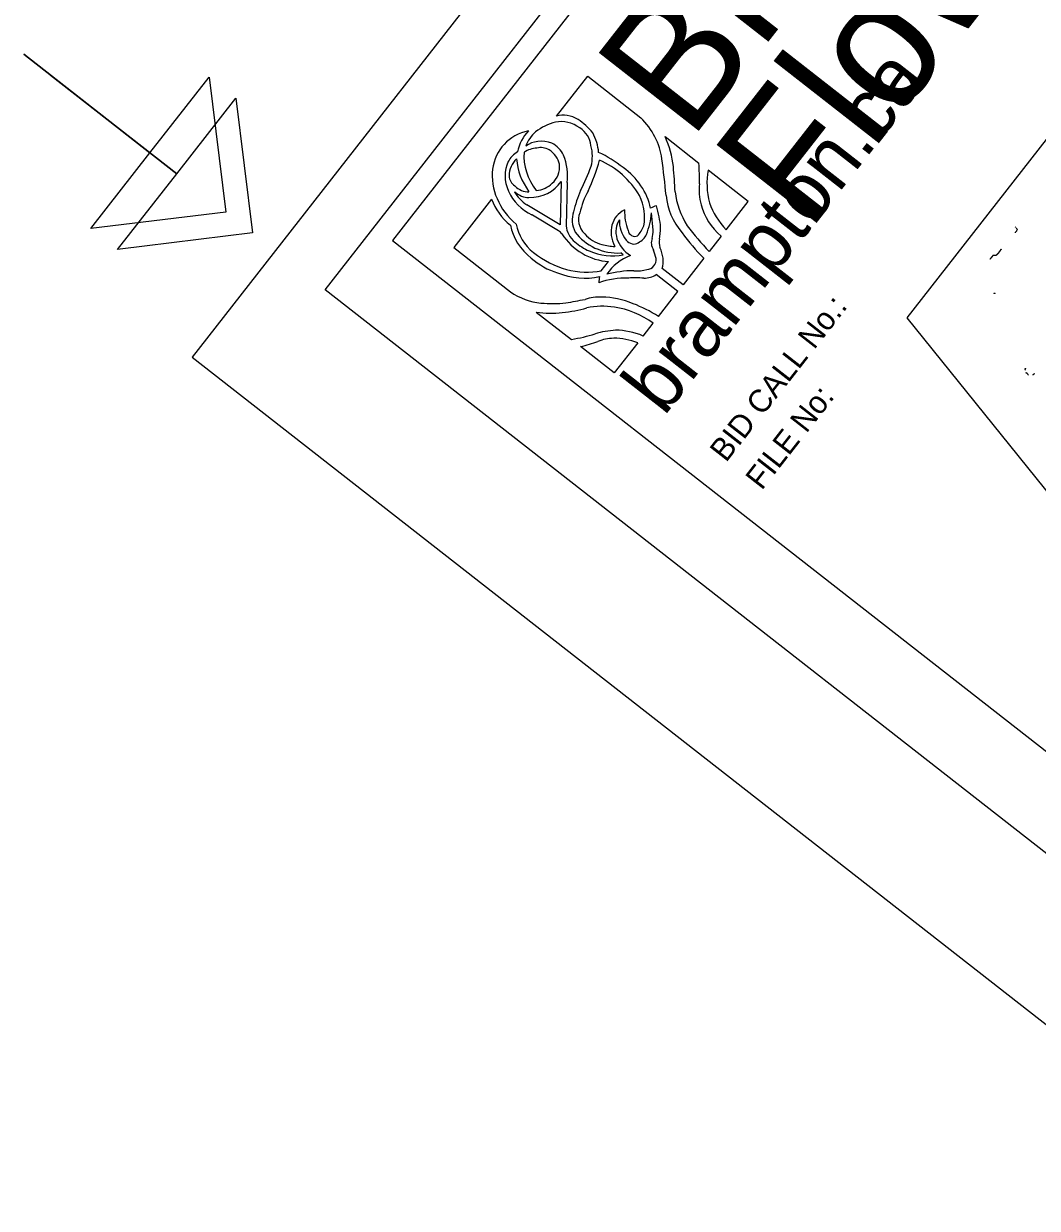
# Model space of a CAD drawing. Extents: x 570310 to 627788, y 4814773 to 4874073.
# Drawn here: x 570310 to 590442, y 4818457 to 4841980 of the extents above; entities that cross this region are included whole.
import ezdxf

# ---------------------------------------------------------------- set-up
doc = ezdxf.new("R2010")
doc.units = 0
for name, color, linetype in [('-PRINT FULLSIZE', 7, 'Continuous'), ('-PRINT HALFSIZE', 7, 'Continuous'), ('ENG_BORDER', 7, 'Continuous'), ('ENG_LOGO', 7, 'Continuous'), ('ENG_TX_BORDER', 7, 'Continuous'), ('ENG_TX_LOGO', 7, 'Continuous'), ('ENG_TX_TITLEBLOCK', 7, 'Continuous'), ('ENG_WK_MISC-1', 7, 'Continuous'), ('GIS_EDGE-WATER', 7, 'Continuous')]:
    doc.layers.add(name, color=color, linetype=linetype)

msp = doc.modelspace()

# ---------------------------------------------------------------- linework, layer by layer
at = {"layer": '-PRINT FULLSIZE'}
msp.add_lwpolyline([(595286.9968, 4818456.8924), (620056.367, 4850160.2405), (598425.4731, 4867060.1469), (573656.1029, 4835356.7988)], close=True, dxfattribs=at)
at = {"layer": '-PRINT HALFSIZE'}
msp.add_lwpolyline([(576300.1305, 4836693.9345), (598958.0147, 4865694.7038), (618744.9647, 4850235.4441), (596087.0805, 4821234.6748)], close=True, dxfattribs=at)
at = {"layer": 'ENG_BORDER'}
msp.add_lwpolyline([(596714.4064, 4822768.5365), (618113.3122, 4850157.887), (599035.5719, 4865063.0513), (577636.6661, 4837673.7008)], close=True, dxfattribs=at)
at = {"layer": 'ENG_LOGO'}
for p, q in [((580895.1142, 4840145.3957), (581513.5575, 4840936.9671)), ((581513.5575, 4840936.9671), (582566.8391, 4840114.0533)), ((583049.1476, 4839737.2326), (583720.5967, 4839212.6391)), ((584698.6494, 4838448.5006), (583903.4326, 4839069.7921)), ((580983.5243, 4838847.5352), (580966.4671, 4837986.3343)), ((581102.0815, 4838826.0463), (581085.0243, 4837964.8454)), ((579603.8661, 4838492.6735), (578854.626, 4837533.6899)), ((580966.4671, 4837986.3343), (580302.4381, 4838384.2037)), ((584262.1791, 4837889.844), (584698.6494, 4838448.5006)), ((580935.4209, 4837866.4397), (580413.2776, 4838179.2948)), ((582813.6306, 4837880.4538), (582781.5828, 4838223.1458)), ((584163.2056, 4837763.1638), (583924.0199, 4837457.02)), ((578854.626, 4837533.6899), (579976.6595, 4836657.0612)), ((582217.4199, 4837389.3826), (582169.062, 4837427.164)), ((581782.586, 4837074.2794), (581926.0648, 4837257.9239)), ((583406.4713, 4836794.5881), (582992.688, 4837117.871)), ((583818.8606, 4837322.4222), (583406.4713, 4836794.5881)), ((583303.374, 4836662.6295), (582870.5051, 4837000.8238)), ((582915.7281, 4836166.4654), (583303.374, 4836662.6295)), ((580491.7344, 4836254.6406), (581187.7589, 4835710.8467)), ((582612.622, 4835778.5072), (582812.6308, 4836034.5068)), ((582039.7179, 4835045.2234), (581370.5948, 4835567.9997)), ((582505.4008, 4835641.2704), (582039.7179, 4835045.2234))]:
    msp.add_line(p, q, dxfattribs=at)
for centre, major_axis, start_param, end_param in [((581109.4813, 4839682.6824), (-419.3161, 327.6057), 4.8589663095, 5.7337363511), ((581380.207, 4838850.902), (-1055.7418, 824.8359), 5.7058114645, 6.0887938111), ((581076.7864, 4839521.9825), (-449.494, 351.1832), 4.7474532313, 5.6817521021), ((580799.8617, 4839251.149), (917.6584, -716.9533), 1.3167113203, 1.6562678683), ((581708.5742, 4839346.5141), (1078.6552, -842.7378), 0.7124777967, 1.4213712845), ((580771.0112, 4838771.248), (-967.9774, 756.2669), 5.6782325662, 7.8074967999), ((581243.3289, 4839050.0378), (-956.7925, 747.5282), 6.2099250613, 6.6775824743), ((581108.2715, 4839163.6651), (-726.8956, 567.9131), 6.1040163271, 6.5523835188), ((581159.7543, 4839592.1523), (-350.6726, 273.9754), 3.823834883, 4.8073067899), ((580771.2477, 4839512.7997), (803.7482, -627.9569), 0.6541881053, 1.0848737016), ((581313.4694, 4839267.1015), (1598.9524, -1249.2385), 0.6826869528, 1.0105277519), ((580626.8192, 4838972.9699), (-469.0218, 366.44), 5.5146652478, 6.0255895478), ((580689.3518, 4839082.5296), (-492.3035, 384.6297), 5.1001923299, 6.0586546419), ((580636.9521, 4839210.7881), (-269.6248, 210.654), 4.9345522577, 5.7209047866), ((580551.2028, 4839174.2787), (340.6053, -266.1101), 0.7855120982, 1.6409488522), ((580624.3392, 4839239.6111), (-383.2821, 299.4528), 4.1958742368, 4.894963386), ((580696.8835, 4839494.2226), (760.2966, -594.0088), 0.3442010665, 0.8318041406), ((580644.4488, 4838838.9882), (647.2744, -505.7061), 3.3189857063, 4.9765849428), ((580479.6761, 4838921.7788), (-501.0843, 391.4899), 5.9370417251, 6.4438162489), ((580521.423, 4838859.9081), (-478.4823, 373.8314), 6.1188819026, 6.855524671), ((581220.4051, 4839163.3753), (-938.3041, 733.0835), 0.6287743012, 1.2559646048), ((581286.267, 4839164.9188), (-869.9484, 679.6782), 0.4842775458, 1.2767125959), ((579925.6813, 4839150.693), (991.437, -774.5955), 0.4608611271, 0.9459223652), ((577521.288, 4840914.9375), (3634.6579, -2839.7059), 0.1774553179, 0.3449817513), ((581127.0734, 4837748.7457), (1650.74, -1289.6995), 1.5652885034, 1.8399595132), ((581350.6476, 4838066.6462), (-1172.8347, 916.3189), 4.2733940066, 5.0058082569), ((561895.012, 4840216.7186), (17792.8211, -13901.2754), 0.6698057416, 0.7058083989), ((580422.482, 4839220.5415), (443.6506, -346.6179), 6.0985748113, 6.9695368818), ((576306.4573, 4841616.0493), (4636.6717, -3622.5649), 0.16181878, 0.2678120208), ((581640.5165, 4838282.4461), (958.684, -749.006), 0.7809699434, 1.6238235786), ((572292.0029, 4840016.7327), (9175.9719, -7169.055), 0.6194507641, 0.6675514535), ((577516.3638, 4839849.6279), (5202.9676, -4065.0038), 0.5738028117, 0.6437425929), ((585595.6575, 4838532.4264), (-1434.863, 1121.0378), 0.4176868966, 0.8184571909), ((580203.4199, 4838936.5287), (-213.1452, 166.5273), 0.6660468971, 1.5760265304), ((580275.1671, 4838945.9347), (-264.5665, 206.702), 1.423327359, 2.3769176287), ((580193.5153, 4839399.7451), (759.9994, -593.7766), 5.4553846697, 6.3466755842), ((580330.1636, 4839240.3471), (504.85, -394.432), 5.5589353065, 6.1986415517), ((584764.1825, 4838500.3192), (-870.4131, 680.0412), 0.4452460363, 0.8692931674), ((580585.2873, 4838856.425), (-516.9259, 403.8667), 1.1195514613, 1.6743983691), ((580428.5899, 4839179.1346), (614.3942, -480.0173), 4.7586960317, 4.9747194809), ((580280.9036, 4838790.588), (228.3375, -178.3968), 4.9898137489, 5.5158032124), ((584281.1905, 4837117.4566), (-2614.249, 2042.4752), 0.2071058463, 0.3649970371), ((583601.192, 4837409.7711), (-1919.1286, 1499.3876), 0.1473665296, 0.3720968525), ((581611.4627, 4838302.5685), (862.7622, -674.0637), 0.4013046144, 1.0207469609), ((584250.16, 4838455.3753), (-991.1305, 774.356), 0.6523004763, 1.3369389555), ((584777.6884, 4838550.9608), (-1288.3363, 1006.5586), 0.690533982, 1.1577139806), ((580492.7588, 4838640.8819), (-788.11, 615.739), 0.9158280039, 1.5687165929), ((582581.9828, 4837749.0811), (-507.647, 396.6173), 5.8789198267, 7.3683806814), ((583252.3059, 4838071.4386), (-843.1948, 658.776), 0.5321884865, 0.9577271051), ((583064.8195, 4837918.407), (-398.5119, 311.3516), 5.6956161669, 5.9785433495), ((580720.5623, 4838115.7052), (1881.8402, -1470.2547), 0.6640190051, 0.8656308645), ((584775.2991, 4838455.4642), (-869.3041, 679.1748), 0.8241736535, 1.5199082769), ((585139.018, 4838632.4005), (-1074.7771, 839.7079), 0.9231161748, 1.3985304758), ((580380.6219, 4838117.7857), (65.2496, -50.9785), 1.7178886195, 1.8349922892), ((581783.1071, 4837994.5493), (-484.7976, 378.7654), 0.2845497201, 1.0288536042), ((581700.5678, 4838029.1459), (-312.1148, 243.8508), 0.1795880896, 1.4251032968), ((582569.7364, 4837771.2011), (416.6051, -325.4876), 3.1733767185, 4.8655067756), ((582659.8973, 4837951.5721), (-433.4004, 338.6095), 0.4777442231, 1.3245705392), ((580697.2995, 4838755.1335), (1752.4651, -1369.1758), 0.2526400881, 0.4825595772), ((580913.8958, 4837994.6653), (-798.8602, 624.138), 0.7643207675, 1.5717221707), ((580879.3938, 4837989.6404), (-666.3815, 520.6343), 0.7413901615, 1.5637538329), ((580870.1095, 4837743.4213), (-130.4991, 101.9571), 4.3258897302, 4.8594812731), ((581811.8142, 4838204.2596), (-827.6886, 646.6612), 1.1842970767, 2.265824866), ((581489.1919, 4837920.7898), (-338.8027, 264.7017), 0.6370603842, 1.5405225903), ((581893.0117, 4838220.416), (-679.4012, 530.8064), 1.258523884, 1.8538737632), ((581826.1035, 4838071.432), (-425.5097, 332.4446), 1.3269106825, 2.0906940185), ((582431.1775, 4837866.748), (-96.9735, 75.764), 0.6934943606, 2.7954406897), ((581836.5339, 4838359.526), (701.6088, -548.1569), 6.2064134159, 6.5196171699), ((581599.0048, 4838127.4485), (1017.3849, -794.8682), 0.3900627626, 0.5372324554), ((581399.8809, 4838202.7278), (1306.6822, -1020.892), 0.4081491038, 0.5667561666), ((585778.9229, 4839131.4658), (-2500.7429, 1953.7945), 1.2235724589, 1.4346288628), ((587371.3177, 4840353.6116), (-4210.7678, 3289.8124), 1.2686065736, 1.395257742), ((581866.416, 4838376.4538), (895.5162, -699.654), 4.6862197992, 4.981796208), ((581914.5138, 4838268.7868), (620.4809, -484.7728), 5.1310282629, 5.4773020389), ((582403.8794, 4837762.5608), (-137.2504, 107.2317), 1.287529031, 2.8996417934), ((582250.4774, 4838036.5476), (390.2618, -304.9059), 5.8964106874, 6.4660989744), ((583042.8761, 4837585.0823), (-223.863, 174.9009), 0.214109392, 1.1533092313), ((583366.1691, 4837566.0401), (-362.3792, 283.1217), 0.4224034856, 0.821660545), ((581253.1562, 4838439.9326), (-1217.0748, 950.8831), 1.5557378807, 2.5226511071), ((581827.1209, 4838391.5769), (893.4609, -698.0482), 5.0194878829, 5.6658955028), ((581941.532, 4838362.449), (818.3835, -639.3913), 4.9954134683, 5.5264632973), ((583033.3397, 4836192.4071), (-1105.1575, 863.4437), 5.8232020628, 6.3340773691), ((581319.3434, 4837198.516), (1339.9159, -1046.857), 0.8288882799, 0.9384559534), ((582395.1724, 4837362.8683), (516.7857, -403.7572), 0.3240202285, 1.04896782), ((581073.5234, 4838049.3467), (-934.6845, 730.2556), 1.4938449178, 2.0023458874), ((582614.4912, 4837340.8751), (215.1815, -168.1182), 5.5817956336, 6.9415708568), ((581225.3227, 4838268.2229), (1170.7994, -914.7287), 5.0636804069, 5.674397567), ((582299.132, 4836754.0713), (-472.1143, 368.8562), 0.3655220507, 0.5978053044), ((582582.7927, 4835264.4236), (-1455.0093, 1136.7778), 5.4396406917, 5.8009467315), ((582925.165, 4834569.3006), (-2189.0357, 1710.2621), 5.4827327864, 5.6973383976), ((583781.4589, 4829492.6448), (-6495.8138, 5075.0859), 5.4413205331, 5.4802135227), ((582351.8851, 4837876.3398), (701.5498, -548.1108), 5.382988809, 5.7042643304), ((582566.2603, 4837350.7232), (368.2043, -287.6727), 5.4231993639, 6.0552075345), ((580497.9163, 4837460.1595), (900.1382, -703.2651), 4.7857115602, 5.3705319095), ((580382.2039, 4838885.1006), (2150.0087, -1679.7709), 5.3697551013, 5.5662623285), ((562680.6847, 4887665.7482), (45424.3859, -35489.4198), 5.6374498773, 5.6449125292), ((581914.3767, 4835629.1811), (-805.6946, 629.4776), 5.4168757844, 5.7837802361), ((582033.4468, 4835200.7677), (-1178.9461, 921.0936), 5.0180265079, 5.4623527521), ((581995.3089, 4834647.4847), (-1668.2179, 1303.3547), 4.811691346, 5.0799693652), ((580490.0222, 4837832.2637), (1397.9682, -1092.2125), 5.2926657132, 5.6050766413), ((580415.6661, 4838565.4312), (2029.7142, -1585.7865), 5.5371185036, 5.753810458), ((582091.5422, 4834785.062), (-1383.179, 1080.6579), 5.3206544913, 5.6595354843), ((582051.4108, 4834913.8869), (-1274.2594, 995.5605), 4.7681195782, 5.2967737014), ((579934.5669, 4839346.9051), (3216.5797, -2513.0675), 5.6237616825, 5.7571961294), ((582606.0022, 4833804.3283), (-1830.5999, 1430.2214), 5.540505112, 5.7388632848), ((582243.3662, 4834726.7907), (-879.8433, 687.409), 5.4979170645, 5.8174834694), ((582232.9061, 4834688.7914), (-912.6358, 713.0292), 5.039091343, 5.480629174), ((582276.487, 4834686.7548), (-1054.5621, 823.9142), 5.0216237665, 5.4584738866), ((580150.7216, 4838521.1251), (2645.2935, -2066.7298), 5.6878483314, 5.8095739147)]:
    msp.add_ellipse(centre, major_axis=major_axis, ratio=0.8372093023, start_param=start_param, end_param=end_param, dxfattribs=at)
at = {"layer": 'ENG_TX_BORDER'}
for points in [[(574321.6155, 4838239.7198), (571641.7409, 4837910.6726), (572817.1546, 4839415.1335), (570309.7197, 4841374.1563), (572817.1546, 4839415.1335), (573992.5682, 4840919.5944)], [(574853.5227, 4837824.1483), (572173.6481, 4837495.1011), (573349.0618, 4838999.562), (570841.627, 4840958.5848), (573349.0618, 4838999.562), (574524.4755, 4840504.0229)]]:
    msp.add_lwpolyline(points, close=True, dxfattribs=at)
at = {"layer": 'ENG_WK_MISC-1'}
msp.add_lwpolyline([(587857.972, 4836141.5321), (604839.9334, 4857877.4515), (606187.3957, 4856824.6986), (612276.2754, 4844401.032), (607413.8593, 4836463.2118), (597417.5611, 4824284.6929)], close=True, dxfattribs=at)
at = {"layer": 'GIS_EDGE-WATER'}
for points in [[(590000, 4837944.4792), (590006.8888, 4837937.648), (590011.8324, 4837932.7456)], [(590021.6136, 4837922.8944), (590028.9372, 4837916.0852), (590035.614, 4837909.8772), (590042.4524, 4837902.5808), (590045.394, 4837899.442), (590047.062, 4837896.2548), (590047.2372, 4837892.1544), (590043.7468, 4837885.5248), (590037.6188, 4837877.6224), (590031.4908, 4837869.72), (590026.4592, 4837863.2312), (590020.2516, 4837855.3912), (590014.0444, 4837847.5512), (590007.8368, 4837839.7108), (590001.8908, 4837832.2012), (590000, 4837829.7488)], [(589551.1832, 4837363.0064), (589550.4592, 4837362.2824), (589549.8076, 4837361.486), (589549.156, 4837360.6896), (589548.468, 4837359.7844), (589547.78, 4837358.9516), (589547.056, 4837358.1552), (589546.332, 4837357.3588), (589545.8252, 4837356.49), (589545.282, 4837355.5848), (589544.7752, 4837354.5712), (589544.3408, 4837353.5572), (589543.87, 4837352.6524), (589543.2908, 4837351.7832), (589542.6392, 4837350.7696), (589541.9512, 4837349.8644), (589541.1912, 4837349.1044), (589540.3944, 4837348.3076), (589539.6704, 4837347.5836), (589538.874, 4837346.7872), (589538.15, 4837346.0632), (589537.3896, 4837345.3752), (589536.6292, 4837344.6148), (589535.8692, 4837343.8548), (589535.0724, 4837342.9856), (589534.3484, 4837342.2616), (589533.5884, 4837341.5016), (589532.7556, 4837340.6688), (589532.0316, 4837339.9448), (589531.2712, 4837339.1844), (589530.5108, 4837338.424), (589529.7508, 4837337.664), (589528.954, 4837336.8672), (589528.194, 4837336.1072), (589527.3612, 4837335.2744), (589526.5648, 4837334.3332), (589525.732, 4837333.428), (589525.044, 4837332.5952), (589524.3924, 4837331.654), (589523.8492, 4837330.7488), (589523.234, 4837329.8436), (589522.6184, 4837328.9388), (589521.9668, 4837327.9976), (589521.2788, 4837327.1648), (589520.5548, 4837326.296), (589519.8308, 4837325.4992), (589519.1068, 4837324.7028), (589518.3828, 4837323.9788), (589517.6224, 4837323.146), (589517.0432, 4837322.2772), (589516.3188, 4837321.336), (589515.6672, 4837320.5396), (589515.052, 4837319.7068), (589514.364, 4837318.8016), (589513.7124, 4837318.0052), (589513.0968, 4837317.1), (589512.3728, 4837316.3036), (589511.6488, 4837315.4348), (589511.0332, 4837314.602), (589510.3452, 4837313.8416), (589509.6576, 4837313.0816), (589508.9332, 4837312.3572), (589508.1368, 4837311.5608), (589507.4852, 4837310.7644), (589506.8696, 4837309.8592), (589506.182, 4837309.0264), (589505.6028, 4837308.1576), (589504.8784, 4837307.3612), (589504.1908, 4837306.456), (589503.5392, 4837305.5872), (589502.8512, 4837304.7544), (589502.1272, 4837303.8132), (589501.2944, 4837302.908), (589500.498, 4837301.9668), (589500, 4837301.4212)], [(589646.7252, 4837399.6084), (589645.9288, 4837398.812), (589645.2412, 4837398.052), (589644.4808, 4837397.2916), (589643.6844, 4837396.4228), (589643.0324, 4837395.5536), (589642.236, 4837394.7572), (589641.4032, 4837393.9244), (589640.6792, 4837393.128), (589639.9916, 4837392.368), (589639.1588, 4837391.5352), (589638.4708, 4837390.7748), (589637.7468, 4837390.0508), (589636.914, 4837389.3628), (589636.0092, 4837388.6752), (589635.1764, 4837387.9148), (589634.4524, 4837387.1908), (589633.692, 4837386.358), (589632.968, 4837385.634), (589632.2076, 4837384.8736), (589631.4112, 4837384.0772), (589630.506, 4837383.2444), (589629.6732, 4837382.4116), (589628.8768, 4837381.76), (589627.8992, 4837381.1448), (589626.922, 4837380.7464), (589625.8356, 4837380.4568), (589624.822, 4837380.1672), (589623.736, 4837379.95), (589622.722, 4837379.8052), (589621.636, 4837379.5156), (589620.55, 4837379.226), (589619.5364, 4837379.226), (589618.4864, 4837379.262), (589617.364, 4837379.3708), (589616.2056, 4837379.3708), (589614.9744, 4837379.2984), (589613.8884, 4837379.0808), (589612.8748, 4837378.8636), (589611.8612, 4837378.7188), (589610.7024, 4837378.8636), (589609.58, 4837379.1896), (589608.458, 4837379.5156), (589607.2992, 4837379.7328), (589606.1772, 4837379.9136), (589605.0548, 4837380.0224), (589604.0048, 4837379.9136), (589602.8824, 4837379.8052), (589601.8688, 4837380.0224), (589600.7828, 4837380.0948), (589599.6964, 4837379.8776), (589598.6104, 4837379.588), (589597.5604, 4837379.5516), (589596.438, 4837379.588), (589595.352, 4837379.6604), (589594.3744, 4837379.9136), (589593.2524, 4837380.0224), (589592.2384, 4837379.95), (589591.08, 4837379.8052), (589589.994, 4837379.7328), (589588.98, 4837379.8052), (589587.894, 4837380.0948), (589586.844, 4837380.2756), (589585.758, 4837380.2756), (589584.5632, 4837380.1672), (589583.3684, 4837379.986), (589582.2464, 4837379.7328), (589581.2324, 4837379.5156), (589580.2188, 4837379.2984), (589579.0964, 4837379.0448), (589578.0468, 4837378.9364), (589576.9244, 4837378.9), (589575.9104, 4837378.8276), (589574.8608, 4837378.574), (589573.7744, 4837378.212), (589572.7972, 4837377.9588), (589571.6024, 4837377.9948), (589570.3712, 4837377.9224), (589569.2852, 4837377.7052), (589568.1268, 4837377.3432), (589566.9684, 4837376.9812), (589565.9184, 4837376.6552), (589564.9048, 4837376.2208), (589563.8908, 4837375.714), (589562.8772, 4837375.1348), (589561.936, 4837374.5556), (589561.0308, 4837373.7228), (589560.162, 4837372.854), (589559.3292, 4837372.0212), (589558.6412, 4837371.1884), (589558.026, 4837370.2836), (589557.1932, 4837369.4508), (589556.4328, 4837368.6904), (589555.7088, 4837367.9664), (589555.0208, 4837367.206), (589554.1884, 4837366.3736), (589553.464, 4837365.5768), (589552.704, 4837364.8168), (589551.98, 4837363.948), (589551.1832, 4837363.0064)], [(589679.9, 4837442.0456), (589679.2848, 4837441.1408), (589678.5968, 4837440.2356), (589677.9452, 4837439.3668), (589677.2212, 4837438.4976), (589676.4972, 4837437.6288), (589675.8092, 4837436.5064), (589675.3024, 4837435.6376), (589674.542, 4837434.5152), (589673.8904, 4837433.6464), (589673.094, 4837432.488), (589672.5144, 4837431.6192), (589671.7904, 4837430.6052), (589671.1388, 4837429.8088), (589670.4508, 4837428.9036), (589669.8356, 4837428.0712), (589669.3648, 4837427.166), (589668.6768, 4837426.2608), (589667.8444, 4837425.3556), (589667.1204, 4837424.5592), (589666.4324, 4837423.7264), (589665.7444, 4837422.8216), (589665.0928, 4837422.0252), (589664.586, 4837421.156), (589663.862, 4837420.2148), (589663.1376, 4837419.2736), (589662.5584, 4837418.26), (589661.9432, 4837417.2824), (589661.2552, 4837416.3772), (589660.6036, 4837415.5808), (589659.8072, 4837414.7844), (589659.0468, 4837414.024), (589658.2864, 4837413.2636), (589657.5984, 4837412.5032), (589656.8744, 4837411.7068), (589656.3316, 4837410.802), (589655.752, 4837409.9328), (589655.3176, 4837408.9916), (589654.63, 4837408.0864), (589653.9056, 4837407.3624), (589653.1816, 4837406.566), (589652.494, 4837405.8056), (589651.806, 4837405.0452), (589651.082, 4837404.3212), (589650.3216, 4837403.6336), (589649.4888, 4837403.018), (589648.6924, 4837402.294), (589648.0768, 4837401.4612), (589647.3528, 4837400.6648), (589646.6652, 4837399.9044), (589646.7252, 4837399.6084)], [(589723.3572, 4837500), (589722.8744, 4837499.2116), (589722.2224, 4837498.1256), (589721.5708, 4837497.3292), (589720.7744, 4837496.46), (589719.9056, 4837495.5912), (589718.9644, 4837494.65), (589718.0228, 4837493.6364), (589717.0452, 4837492.6588), (589716.3576, 4837491.8984), (589715.344, 4837490.8124), (589714.3664, 4837489.7624), (589713.4976, 4837488.8212), (589712.7372, 4837488.0608), (589712.0492, 4837487.3004), (589711.1804, 4837486.3592), (589710.384, 4837485.418), (589709.66, 4837484.4044), (589709.0444, 4837483.4268), (589708.5012, 4837482.5216), (589707.922, 4837481.5804), (589707.4152, 4837480.5668), (589706.7996, 4837479.5168), (589706.112, 4837478.5392), (589705.424, 4837477.4892), (589704.8448, 4837476.6204), (589704.1568, 4837475.6428), (589703.4328, 4837474.5568), (589702.8536, 4837473.4708), (589702.3468, 4837472.6016), (589701.6588, 4837471.8416), (589700.8624, 4837470.9), (589700.0656, 4837469.8864), (589699.378, 4837468.9088), (589698.8348, 4837468.004), (589698.2916, 4837467.0988), (589697.7488, 4837466.0488), (589697.3504, 4837464.9988), (589696.7712, 4837463.9128), (589696.192, 4837462.9716), (589695.504, 4837461.994), (589694.7076, 4837460.9804), (589693.9836, 4837460.0392), (589693.2956, 4837459.134), (589692.644, 4837458.1928), (589691.8836, 4837457.1428), (589691.0508, 4837456.1652), (589690.2908, 4837455.26), (589689.6392, 4837454.4636), (589689.132, 4837453.5948), (589688.372, 4837452.6172), (589687.5032, 4837451.5312), (589686.5616, 4837450.5176), (589685.6928, 4837449.576), (589684.8964, 4837448.7796), (589684.136, 4837447.8744), (589683.4844, 4837447.0056), (589682.7964, 4837446.1004), (589682, 4837445.1592), (589681.2396, 4837444.1092), (589680.5156, 4837443.0232), (589679.9, 4837442.0456)], [(589596.9488, 4836625.3968), (589596.9688, 4836624.3416), (589596.8452, 4836623.2684), (589596.3044, 4836622.3268), (589595.6424, 4836621.4796), (589594.81, 4836620.83), (589593.978, 4836620.1808), (589593.1368, 4836619.6032), (589592.2064, 4836619.1608), (589591.16, 4836619.0688), (589590.2812, 4836619.6904), (589589.4744, 4836620.3208), (589588.5464, 4836621.046), (589587.6812, 4836621.8516), (589586.8972, 4836622.5944), (589586.1532, 4836623.3052), (589585.504, 4836624.1376), (589585.228, 4836625.198), (589585.2708, 4836626.334), (589585.6504, 4836627.402), (589586.3436, 4836628.2896), (589587.0056, 4836629.1368), (589587.6992, 4836630.0244), (589588.3296, 4836630.8312), (589588.96, 4836631.638), (589589.6712, 4836632.382), (589590.5124, 4836632.9596), (589591.3848, 4836633.5772), (589592.4048, 4836633.8848), (589593.4776, 4836633.7612), (589594.2848, 4836633.1308), (589595.0284, 4836632.4196), (589595.5832, 4836631.4664), (589595.8504, 4836630.478), (589596.158, 4836629.458), (589596.2816, 4836628.452), (589596.9488, 4836625.3968)], [(590209.9984, 4835140.0492), (590210.8232, 4835137.7404), (590210.7296, 4835135.2224), (590208.9156, 4835132.9), (590204.7356, 4835130.5244), (590199.3056, 4835128.3384), (590196.2896, 4835124.9068), (590194.7316, 4835122.2592), (590195.226, 4835119.2244), (590198.3244, 4835113.3268), (590198.2472, 4835106.6908), (590198.6688, 4835102.2496), (590200.6096, 4835098.8532)], [(590257.4516, 4835000), (590259.5164, 4835004.2744), (590260.2988, 4835008.1384), (590258.7232, 4835011.5016), (590249.4608, 4835024.3872), (590246.608, 4835026.9212), (590244.3652, 4835030.2556), (590243.742, 4835033.6304), (590241.1372, 4835035.5188), (590238.1648, 4835038.358), (590233.9532, 4835040.228), (590229.4612, 4835042.5848), (590222.5464, 4835043.562), (590219.4464, 4835044.0808), (590216.2784, 4835044.9932)], [(590384.9524, 4835030.2012), (590383.0656, 4835027.2408), (590377.8984, 4835022.7452), (590371.7988, 4835017.8128), (590367.4956, 4835016.2472), (590363.3932, 4835015.5416), (590359.588, 4835013.0976), (590356.7304, 4835008.8648), (590354.5304, 4835002.5972), (590354.0772, 4835000)]]:
    msp.add_lwpolyline(points, dxfattribs=at)

# ---------------------------------------------------------------- texts
at = {"layer": 'ENG_TX_LOGO'}
msp.add_text('brampton.ca', height=1147.5, rotation=52, dxfattribs=at).set_placement((583027.4945, 4834166.6251))
at = {"layer": 'ENG_TX_TITLEBLOCK'}
for s, height, p in [('BRAMPTON', 2520, (583548.1841, 4839634.039)), ('Flower City', 2520, (585888.5761, 4837805.5244)), ('BID CALL No.: ', 449.999928, (584259.2939, 4833253.3203)), ('FILE No: ', 449.99993, (584968.5035, 4832699.2251))]:
    msp.add_text(s, height=height, rotation=52, dxfattribs=at).set_placement(p)

doc.saveas('drawing.dxf')
